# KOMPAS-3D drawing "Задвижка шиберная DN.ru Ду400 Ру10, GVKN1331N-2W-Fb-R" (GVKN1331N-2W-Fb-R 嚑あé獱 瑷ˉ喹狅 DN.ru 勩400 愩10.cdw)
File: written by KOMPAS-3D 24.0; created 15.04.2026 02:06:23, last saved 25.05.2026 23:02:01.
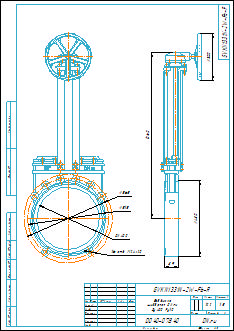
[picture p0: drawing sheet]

Document properties: Автор: DN.ru; Форматы листов документа: A3; Полное имя файла: GVKN1331N-2W-Fb-R Задвижка шиберная DN.ru Ду400 Ру10.m3d; Масса: 122; Наименование: Задвижка шиберная DN.ru Ду400 Ру10; Количество листов документа: 1; Примечание: D040-07840

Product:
- Part/product: Задвижка шиберная DN.ru Ду400 Ру10  | designation GVKN1331N-2W-Fb-R
    Масса: 122
    Раздел спецификации: Прочие изделия
    Примечание: D040-07840

Views: Вид 1, Вид:1
Referenced files in C:\Работа\GVKN1331N-2W-Fb-R Задвижка шиберная DN.ru Ду400-600 Ру10\DN400\: GVKN1331N-2W-Fb-R Задвижка шиберная DN.ru Ду400 Ру10.m3d
Referenced files in C:\Program Files\ASCON\KOMPAS-3D v24\Templates\: Чертеж_DN.ru.cdt
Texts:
  DN400
  GVKN1331N-2W-Fb-R
  Чертеж_DN.ru.cdt
  Задвижка
  шиберная DN.ru
  Ду400 Ру10
  Задвижка шиберная DN.ru Ду400 Ру10
  GVKN1331N-2W-Fb-R Задвижка шиберная DN.ru Ду400 Ру10
Dimensions and other numbers on the sheet: 0; 3; 2; 4; 565; 515; 16 отв.; 24; 1; 1:5; 122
